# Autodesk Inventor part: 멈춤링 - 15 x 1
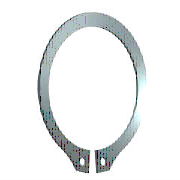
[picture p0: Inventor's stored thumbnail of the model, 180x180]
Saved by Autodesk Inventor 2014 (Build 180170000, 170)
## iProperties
Created: 2015-09
Part Number: 멈춤링 - 15 x 1
Material: 강, 연강
Description: 리테이닝 링(C형)
Document SubType Name: Modeling
Standard: KS B 1336
Designer: mm
Standards Organization: KS
Language: ko-KR
Size Designation: 15 x 1
Categories: <MemberInstance><Categories><Category DisplayName="샤프트 부품" InternalName="7f7aeb1f-a693-4053-b835-cee3144e0d98" Mnemonic="SHFT"><Category DisplayName="써클립" Inter
Density: 1 g/cm^3
Appearance: 광택 - 검은색
IsCustomPart: 1
Author: mduedu
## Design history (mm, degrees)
sketch "스케치1"
  geometry: L1 (-6, 0)-(6, 0) reference; L2 (0, 20.189)-(0, -80.536) reference; L3 (-48.09, 0)-(48.09, 0) reference; L4 (-0.425, -14.637)-(-0.425, -18.137); L5 (-0.425, -6.54)-(-0.425, -13.29); L6 (-2.795, 2.1)-(3.672, 2.1); L7 (0.425, -6.54)-(0.425, -13.29); L8 (0.425, -14.637)-(0.425, -18.137); C1 r 0.85 at (-1.7, -16.283); C2 r 0.85 at (1.7, -16.283); A1 r 7.15 centre (0, -7.5) between (0.425, -14.637) and (-0.425, -14.637); A2 r 9.075 centre (0, -6.975) between (4.291, -14.971) and (-4.291, -14.971); A3 r 10.646 centre (0, -7.5) between (-2.023, -17.952) and (-0.425, -18.137); A4 r 1.7 centre (-1.7, -16.283) between (-3.397, -16.376) and (-2.023, -17.952); A5 r 1.7 centre (-5.095, -16.469) between (-3.397, -16.376) and (-4.291, -14.971); A6 r 1.7 centre (5.095, -16.469) between (4.291, -14.971) and (3.397, -16.376); A7 r 1.7 centre (1.7, -16.283) between (2.023, -17.952) and (3.397, -16.376); A8 r 10.646 centre (0, -7.5) between (0.425, -18.137) and (2.023, -17.952)
  constraints: 16 point on circle, 12 end point, 10 centre point, 9 symmetric about line, 5 point on line, 4 tangent, 3 coincident, 2 horizontal, 1 perpendicular, 1 vertical, 5 other
  dimensions: "d0" = 14.3 diameter of A1 (= ND); "d1" = 3.5 distance of L4.end L4.start (= SRB2); "d6" = 0.425 distance between parallel lines of L2 L5 (= 0.25 x SD5); "d7" = 2.1 distance between parallel lines of L6 L3 (= SRB1); "d8" = 0.525 distance of A1.centre A2.centre (= 0.25 x SRB1); "d9" = 1.7 radius of A4 (= SD5); "d10" = 1.7 radius of A5 (= SD5); "d11" = 1.275 distance from line of L4 A4.centre (= 0.75 x SD5); "d12" = 1.7 diameter of C1 (= SD5); "d13" = 1.7 diameter of C2 (= SD5); "d14" = 7.5 distance from line of A1.centre L1 (= 0.5 x WD)
extrude "본체" new body sketch "스케치1" distance "d2" = 1 (= SD); taper "d3" = 0 deg
workaxis "Work Axis1"
workplane "Work Plane1"
body "Solid1"
other parameters: "WD" = 15 (= WDMIN) [user parameter; used in 1 equation term], "SD" = 1 [user parameter; used in 1 equation term], "SRB1" = 2.1 [user parameter; used in 2 equation terms], "ND" = 14.3 [user parameter; used in 1 equation term], "SRB2" = 3.5 [user parameter; used in 1 equation term], "SD5" = 1.7 [user parameter; used in 6 equation terms], "d15" = 0, "d16" = 0, "d17" = 0, "d41" = 0, "d42" = 0, "WDMIN" = 15 [user parameter; used in 1 equation term], "SD3" = 13.8 [user parameter], "WDMAX" = 16 [user parameter]
